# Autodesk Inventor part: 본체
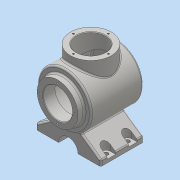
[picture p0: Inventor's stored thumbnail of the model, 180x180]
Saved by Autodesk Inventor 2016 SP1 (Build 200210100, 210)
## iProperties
Created: 2017-04
Part Number: 본체
Material: 일반
Document SubType Name: Modeling
Designer: CAMTIC
Density: 1 g/cm^3
Appearance: 기본값
Author: CAMTIC
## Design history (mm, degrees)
sketch "스케치1"
  geometry: L1 (-50, 50)-(46.336, 50); L2 (46.336, 50)-(46.336, 0); L3 (46.336, 0)-(-50, 0); L4 (-50, 0)-(-50, 50); L5 (-50, 0)-(-62, 0); L6 (-62, 0)-(-62, 38); L7 (-62, 38)-(-50, 38); L8 (-50, 38)-(-50, 0); L9 (0, 0)-(0, 50); L10 (46.336, 0)-(58, 0); A1 r 113 centre (-55, 0) between (58, 0) and (46.336, 50); 1 further point
  constraints: 20 end point, 4 parallel, 3 horizontal, 3 perpendicular, 3 point on line, 2 point on circle, 1 centre point, 1 coincident, 1 horizontal alignment
  dimensions: "d1" = 113 radius of A1; "d2" = 12 distance of L6.end L7.end; "d4" = 100 diameter of L1 L3; "d5" = 76 diameter of L7 L5; "d6" = 50 distance between parallel lines of L4 L9; "d8" = 108 distance from line of L4 L10.end
revolve "회전1" sketch "스케치1" stored, may be unused: angle "d9" = 90 deg
sketch "스케치2"
  geometry: C1 r 38 at (0, 0); 1 further point
  constraints: 1 centre point, 1 coincident
  dimensions: "d10" = 76 diameter of C1
extrude "돌출1" join sketch "스케치2" distance "d11" = 65; taper "d12" = 0 deg
node "작업 평면1"
sketch "스케치4"
  geometry: L1 (0, -29.988)-(-60, -72); L2 (-60, -72)-(-60, -82); L3 (-60, -82)-(60, -82); L4 (60, -82)-(60, -72); L5 (60, -72)-(0, -29.988); C1 r 18 at (0, -82); 1 further point
  constraints: 10 end point, 2 equal length, 2 perpendicular, 1 centre point, 1 midpoint, 1 vertical, 1 vertical alignment
  dimensions: "d16" = 55 deg angle of L2 L1; "d17" = 10 distance of L3.end L4.end; "d18" = 36 diameter of C1; "d19" = 120 distance of L2.end L3.end; "d20" = 82 distance from line of L3 point (0, 0)
extrude "돌출2" join sketch "스케치4" distance "d21" = 80; taper "d22" = 0 deg
extrude "돌출3" cut sketch "스케치4" stored distance "d23" = 80; taper "d24" = 0 deg
sketch "스케치5"
  geometry: L1 (-50, -50)-(46.336, -50) reference; L2 (-50, 50)-(46.336, 50) reference; L3 (-50, -50)-(-50, 50) reference; L4 (39.916, 40)-(-40, 40); L5 (-40, 40)-(-40, -40); L6 (-40, -40)-(39.916, -40); L7 (-40, 0)-(48, 0); L8 (-40, 27)-(-62, 27); L9 (-62, 27)-(-62, 0); L10 (-62, 0)-(-40, 0); L11 (-40, 0)-(-40, 27); A1 r 113 centre (-55, 0) between (46.336, -50) and (46.336, 50) reference; A2 r 103 centre (-55, 0) between (39.916, -40) and (39.916, 40); 1 further point
  constraints: 18 end point, 3 point on circle, 2 parallel, 1 centre point, 1 collinear, 1 horizontal, 1 midpoint, 1 perpendicular, 1 point on line, 2 other
  dimensions: "d25" = 10 radial gap between concentric circles of A1 A2; "d26" = 80 distance between parallel lines of L6 L4; "d27" = 22 distance between parallel lines of L5 L9; "d28" = 54 diameter of L8 L7
revolve "회전2" sketch "스케치5" stored, may be unused: angle "d29" = 90 deg
hole "구멍1" diameter "d32" = 54; stored, may be unused: countersink angle "d36" = 90 deg, drill point angle "d38" = 0 deg; dims "d33" = 6, "d34" = 4, "d35" = 2, "d37" = 8, "d41" = 10, "d42" = 10
node "작업 평면2"
sketch "스케치6"
  geometry: L1 (-50, -22)-(-60, -22); L2 (-50, -14)-(-60, -14); L3 (-60, -30)-(-50, -30); L4 (-95.2, 0)-(95.2, 0) reference; L5 (0, -86)-(0, 82) reference; L6 (-60, -42)-(-60, 38) reference; L7 (-21.584, -42)-(-60, -42) reference; L8 (60, -30)-(50, -30); L9 (50, -14)-(60, -14); L10 (50, -22)-(60, -22); L11 (-50, 18)-(-60, 18); L12 (-50, 26)-(-60, 26); L13 (-60, 10)-(-50, 10); L14 (50, 26)-(60, 26); L15 (60, 10)-(50, 10); L16 (50, 18)-(60, 18); A1 r 8 centre (-50, -22) between (-50, -30) and (-50, -14); A2 r 8 centre (-60, -22) between (-60, -14) and (-60, -30); A3 r 8 centre (60, -22) between (60, -30) and (60, -14); A4 r 8 centre (50, -22) between (50, -14) and (50, -30); A5 r 8 centre (-50, 18) between (-50, 10) and (-50, 26); A6 r 8 centre (-60, 18) between (-60, 26) and (-60, 10); A7 r 8 centre (60, 18) between (60, 10) and (60, 26); A8 r 8 centre (50, 18) between (50, 26) and (50, 10); 4 further points
  constraints: 32 end point, 16 point on circle, 13 symmetric about line, 8 centre point, 8 tangent, 3 parallel, 2 horizontal, 2 midpoint, 2 point on line, 1 equal radius, 4 other
  dimensions: "d40" = 8 radius of A1; "d43" = 10 distance from line of L1.start L6; "d44" = 20 distance from line of L7 L1.end; "d114" = 40 distance of L1.end L11.end
extrude "돌출4" cut sketch "스케치6" distance "d45" = 20; taper "d46" = 0 deg
hole "구멍2" diameter "d49" = 8; stored, may be unused: countersink angle "d53" = 90 deg, drill point angle "d55" = 118 deg; dims "d47" = 10, "d48" = 10, "d50" = 6, "d51" = 4, "d52" = 2, "d54" = 8
hole "구멍3" diameter "d58" = 8; stored, may be unused: countersink angle "d62" = 90 deg, drill point angle "d64" = 118 deg; dims "d59" = 6, "d60" = 4, "d61" = 2, "d63" = 8, "d115" = 10, "d116" = 10
hole "구멍4" diameter "d67" = 8; stored, may be unused: countersink angle "d71" = 90 deg, drill point angle "d73" = 118 deg; dims "d65" = 10, "d66" = 10, "d68" = 6, "d69" = 4, "d70" = 2, "d72" = 8
hole "구멍5" diameter "d76" = 8; stored, may be unused: countersink angle "d80" = 90 deg, drill point angle "d82" = 118 deg; dims "d77" = 6, "d78" = 4, "d79" = 2, "d81" = 8, "d117" = 10, "d118" = 10
sketch "스케치8"
  geometry: 2 further points
  constraints: 1 vertical alignment
  dimensions: "d83" = 32.5 distance of point (0, 0) point (0, 32.5)
hole "구멍6" sketch "스케치8" at (0, 32.5) diameter "d84" = 3.242; stored, may be unused: countersink angle "d88" = 90 deg, drill point angle "d90" = 118 deg; dims "d85" = 8, "d86" = 4, "d87" = 2, "d89" = 10
sketch "스케치9"
  geometry: 2 further points
  constraints: 1 horizontal alignment
  dimensions: "d94" = 32.5 distance of point (0, 0) point (-32.5, 0)
hole "구멍7" sketch "스케치9" at (-32.5, 0) diameter "d95" = 3.242; stored, may be unused: countersink angle "d99" = 90 deg, drill point angle "d101" = 118 deg; dims "d96" = 8, "d97" = 4, "d98" = 2, "d100" = 10
fillet "모깎기1" dims "d105" = 3
chamfer "모따기1" distance "d106" = 1; stored, may be unused: second distance "d107" = 2, angle "d108" = 45 deg
fillet "모깎기2" dims "d109" = 3
fillet "모깎기3" dims "d110" = 3
fillet "모깎기4" dims "d111" = 3
fillet "모깎기5" dims "d112" = 3
fillet "모깎기6" dims "d113" = 3
node "작업 평면3"
sketch "스케치11"
  geometry: 2 further points
  constraints: 1 coincident, 1 other
feature "엠보싱1" sketch "스케치11" dims "d1" = 113, "d2" = 12, "d4" = 100, "d5" = 76, "d6" = 50, "d8" = 108, "d119" = 0.5, "d120" = 0
node "솔리드1"
pattern_circular "원형 패턴1" dims angle "d92" = 360 deg
pattern_circular "원형 패턴2" dims angle "d103" = 360 deg
other parameters: "d15" = -8, "d39" = -76
